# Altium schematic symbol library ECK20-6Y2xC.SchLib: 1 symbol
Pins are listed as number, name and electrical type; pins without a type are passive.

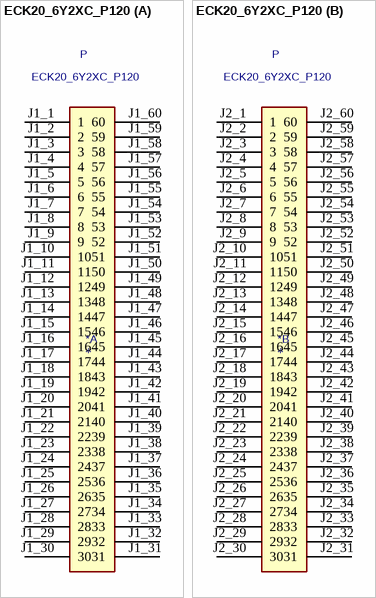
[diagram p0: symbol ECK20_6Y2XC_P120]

## ECK20_6Y2XC_P120
designator *  value ECK20_6Y2XC_P120  Reference: P
part A pins: J1_1 1, J1_2 2, J1_3 3, J1_4 4, J1_5 5, J1_6 6, J1_7 7, J1_8 8, J1_9 9, J1_10 10, J1_11 11, J1_12 12, J1_13 13, J1_14 14, J1_15 15, J1_16 16, J1_17 17, J1_18 18, J1_19 19, J1_20 20, J1_21 21, J1_22 22, J1_23 23, J1_24 24, J1_25 25, J1_26 26, J1_27 27, J1_28 28, J1_29 29, J1_30 30, J1_31 31, J1_32 32, J1_33 33, J1_34 34, J1_35 35, J1_36 36, J1_37 37, J1_38 38, J1_39 39, J1_40 40, J1_41 41, J1_42 42, J1_43 43, J1_44 44, J1_45 45, J1_46 46, J1_47 47, J1_48 48, J1_49 49, J1_50 50, J1_51 51, J1_52 52, J1_53 53, J1_54 54, J1_55 55, J1_56 56, J1_57 57, J1_58 58, J1_59 59, J1_60 60
part B pins: J2_1 1, J2_2 2, J2_3 3, J2_4 4, J2_5 5, J2_6 6, J2_7 7, J2_8 8, J2_9 9, J2_10 10, J2_11 11, J2_12 12, J2_13 13, J2_14 14, J2_15 15, J2_16 16, J2_17 17, J2_18 18, J2_19 19, J2_20 20, J2_21 21, J2_22 22, J2_23 23, J2_24 24, J2_25 25, J2_26 26, J2_27 27, J2_28 28, J2_29 29, J2_30 30, J2_31 31, J2_32 32, J2_33 33, J2_34 34, J2_35 35, J2_36 36, J2_37 37, J2_38 38, J2_39 39, J2_40 40, J2_41 41, J2_42 42, J2_43 43, J2_44 44, J2_45 45, J2_46 46, J2_47 47, J2_48 48, J2_49 49, J2_50 50, J2_51 51, J2_52 52, J2_53 53, J2_54 54, J2_55 55, J2_56 56, J2_57 57, J2_58 58, J2_59 59, J2_60 60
